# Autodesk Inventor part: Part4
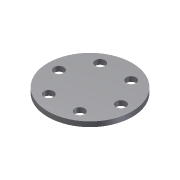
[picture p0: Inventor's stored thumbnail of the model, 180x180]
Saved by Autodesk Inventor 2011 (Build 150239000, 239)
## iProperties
Created: 2008-05
Part Number: Part4
Document SubType Name: Modeling
Designer: CADCIM
Density: 1 g/cm^3
Author: CADCIM
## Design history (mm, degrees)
sketch "Sketch1"
  geometry: C1 r 17 at (0, 0)
  constraints: 1 centre point, 1 other
  dimensions: "d12" = 34 diameter of C1
extrude "Extrusion1" new body sketch "Sketch1" distance "d0" = 2; taper "d1" = 0 deg
sketch "Sketch2"
  geometry: 1 further point
hole "Hole1" sketch "Sketch2" at (5.9, 10.769) diameter "d2" = 4; stored, may be unused: countersink angle "d6" = 90 deg, drill point angle "d8" = 118 deg; dims "d3" = 6, "d4" = 4, "d5" = 2, "d7" = 8
pattern_circular "Circular Pattern1" dims angle "d10" = 360 deg
body "Solid1"
